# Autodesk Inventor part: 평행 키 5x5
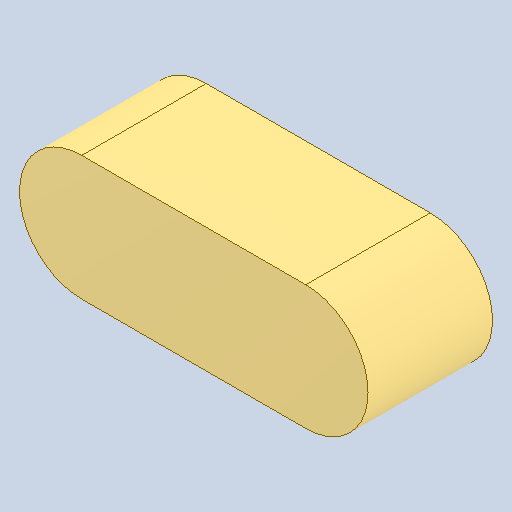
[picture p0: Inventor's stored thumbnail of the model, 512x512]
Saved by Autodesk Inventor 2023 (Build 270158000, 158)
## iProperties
Created: 2025-04
Part Number: 평행 키 5x5
Material: 강철, 연강
Document SubType Name: Modeling
Designer: User
Density: 7.86 g/cm^3
Appearance: 기본값
Author: jhkim
Revision Number: 1
Sending System: Autodesk Inventor 2026
Preprocessor: ST-DEVELOPER v20.1
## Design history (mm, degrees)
feature "솔리드1"
node "솔리드2"
